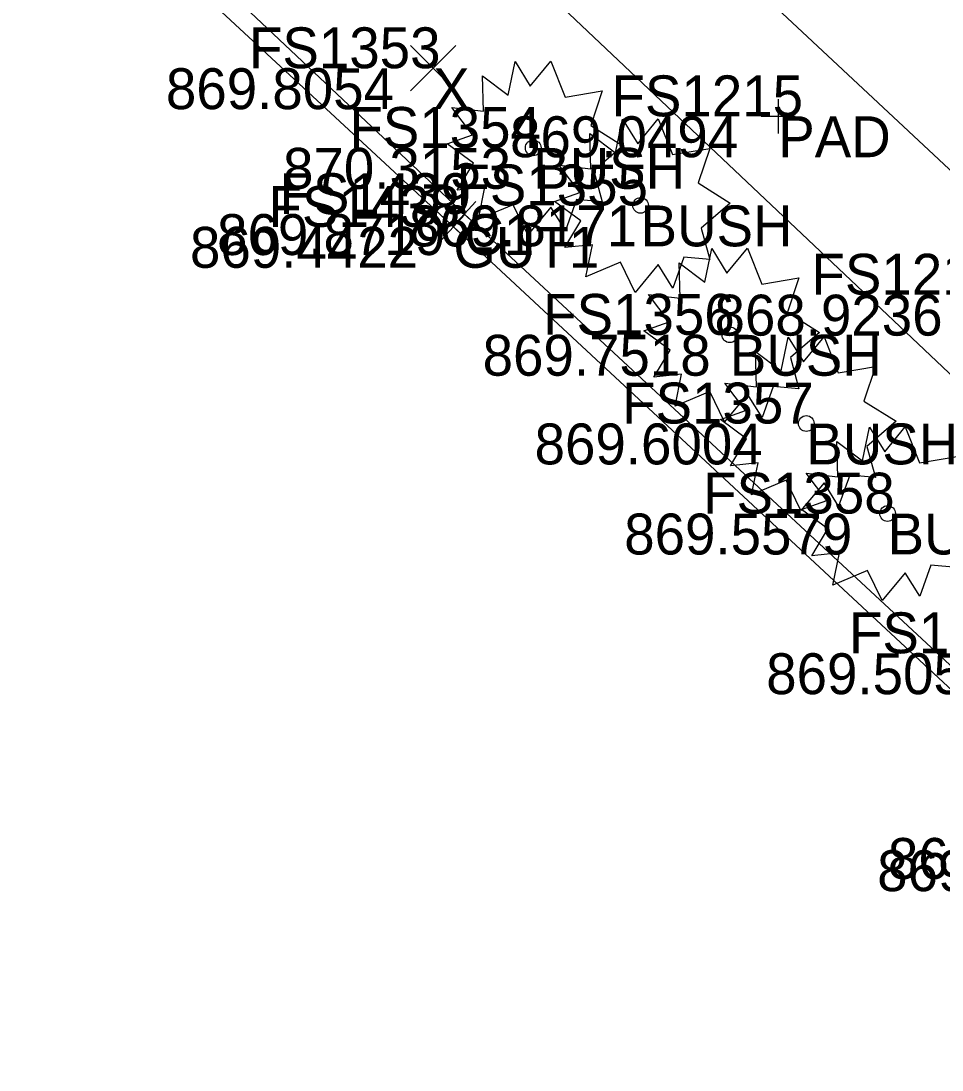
# Model space of a CAD drawing. Extents: x 1469677 to 1493262, y 375219 to 389293.
# Drawn here: x 1479642.82 to 1479669.85, y 379821.94 to 379852.72 of the extents above; entities that cross this region are included whole.
import ezdxf

# ---------------------------------------------------------------- set-up
doc = ezdxf.new("R2010")
doc.units = 0
for name, color, linetype in [('DV_X_Lot_Line', 7, 'Continuous'), ('DV_X_Text', 7, 'Continuous'), ('GK_Visualization', 7, 'Continuous'), ('PNTELEV', 7, 'Continuous'), ('RD_P_Text', 7, 'Continuous'), ('RW_P_Const_Limits', 7, 'Continuous'), ('RW_P_Esmt_SW', 7, 'Continuous'), ('RW_P_Esmt_U', 7, 'Continuous')]:
    doc.layers.add(name, color=color, linetype=linetype)

msp = doc.modelspace()

# ---------------------------------------------------------------- linework, layer by layer
at = {"layer": 'DV_X_Lot_Line'}
for points in [[(1479705.728, 379814.895), (1479685.769, 379833.709), (1479660.411, 379857.395), (1479657.292, 379860.626), (1479660.086, 379863.591), (1479659.321, 379864.377), (1479657.858, 379865.693), (1479656.248, 379867.188), (1479655.369, 379867.882), (1479654.27, 379866.26), (1479652.631, 379864.542), (1479652.351, 379864.607), (1479645.059, 379871.586), (1479642.188, 379874.12), (1479639.084, 379877.042), (1479636.766, 379877.319), (1479635.406, 379877.451), (1479631.457, 379877.615), (1479630.424, 379877.567), (1479629.778, 379877.526), (1479625.011, 379876.78), (1479605.984, 379871.904), (1479600.533, 379870.639), (1479580.734, 379865.6)], [(1479703.027, 379811.462), (1479682.443, 379830.686), (1479657.296, 379854.468), (1479652, 379859.64), (1479649.772, 379861.739), (1479651.803, 379859.818), (1479649.833, 379861.569), (1479642.24, 379868.777), (1479639.038, 379871.891), (1479636.885, 379872.56), (1479634.381, 379872.969), (1479631.754, 379873.282), (1479630.076, 379873.213), (1479625.848, 379872.765), (1479606.823, 379868.193), (1479601.313, 379866.859), (1479581.547, 379861.918)]]:
    msp.add_lwpolyline(points, dxfattribs=at)
at = {"layer": 'PNTELEV'}
for p, q in [((1479665.044, 379850.427), (1479665.044, 379849.427)), ((1479664.544, 379849.927), (1479665.544, 379849.927)), ((1479665.044, 379849.927), (1479665.044, 379849.927)), ((1479656.198, 379846.717), (1479655.466, 379847.397)), ((1479655.492, 379846.69), (1479656.172, 379847.423)), ((1479655.876, 379846.342), (1479655.144, 379847.023)), ((1479655.17, 379846.316), (1479655.85, 379847.048)), ((1479655.832, 379847.057), (1479655.832, 379847.057)), ((1479655.51, 379846.682), (1479655.51, 379846.682))]:
    msp.add_line(p, q, dxfattribs=at)
at = {"layer": 'RD_P_Text'}
for points in [[(1479752.341, 379756.82), (1479734.895, 379773.493), (1479717.229, 379789.662), (1479699.298, 379806.402), (1479688.16, 379794.934), (1479685.526, 379793.897), (1479682.733, 379795.157), (1479681.263, 379797.549), (1479682.493, 379800.746), (1479693.462, 379811.911), (1479675.554, 379828.75), (1479655.832, 379847.057), (1479640.191, 379861.809), (1479628.558, 379849), (1479624.614, 379847.664), (1479622.46, 379848.585), (1479618.996, 379850.857), (1479611.825, 379854.437), (1479601.319, 379856.892), (1479590.521, 379858.039)], [(1479751.933, 379756.629), (1479734.447, 379772.976), (1479716.701, 379789.463), (1479699.4, 379805.742), (1479688.561, 379794.786), (1479685.717, 379793.294), (1479682.291, 379794.8), (1479680.73, 379797.254), (1479682.169, 379801.19), (1479692.652, 379811.907), (1479675.183, 379828.391), (1479655.51, 379846.682), (1479640.151, 379860.926), (1479629.134, 379848.869), (1479624.571, 379847.215), (1479622.228, 379847.911), (1479618.757, 379850.398), (1479611.519, 379853.97), (1479601.347, 379856.369), (1479590.364, 379857.442)]]:
    msp.add_lwpolyline(points, dxfattribs=at)
at = {"layer": 'RW_P_Const_Limits'}
for points in [[(1479657.768, 379850.81), (1479658.373, 379851.545), (1479658.788, 379850.492), (1479659.88, 379850.672), (1479659.541, 379849.66), (1479660.486, 379849.065), (1479659.63, 379848.33), (1479659.88, 379847.417), (1479659.126, 379847.485), (1479658.801, 379846.572), (1479658.373, 379847.264), (1479657.695, 379846.447), (1479657.266, 379847.334), (1479656.246, 379846.904), (1479656.438, 379847.845), (1479655.626, 379847.762), (1479656.1, 379848.552), (1479655.331, 379849.12), (1479656.07, 379849.384), (1479655.463, 379850.187), (1479656.395, 379850.077), (1479656.365, 379851.115), (1479657.118, 379850.547), (1479657.325, 379851.532), (1479657.768, 379850.81)], [(1479660.919, 379849.121), (1479661.524, 379849.856), (1479661.939, 379848.803), (1479663.031, 379848.983), (1479662.692, 379847.971), (1479663.637, 379847.376), (1479662.781, 379846.641), (1479663.031, 379845.728), (1479662.277, 379845.796), (1479661.952, 379844.883), (1479661.524, 379845.574), (1479660.846, 379844.758), (1479660.417, 379845.644), (1479659.397, 379845.214), (1479659.589, 379846.156), (1479658.777, 379846.073), (1479659.251, 379846.863), (1479658.482, 379847.431), (1479659.221, 379847.694), (1479658.614, 379848.498), (1479659.546, 379848.388), (1479659.516, 379849.426), (1479660.269, 379848.858), (1479660.476, 379849.843), (1479660.919, 379849.121)], [(1479663.539, 379845.325), (1479664.144, 379846.06), (1479664.559, 379845.006), (1479665.651, 379845.186), (1479665.312, 379844.175), (1479666.257, 379843.58), (1479665.401, 379842.845), (1479665.651, 379841.931), (1479664.897, 379842), (1479664.572, 379841.086), (1479664.144, 379841.778), (1479663.466, 379840.961), (1479663.037, 379841.848), (1479662.017, 379841.418), (1479662.209, 379842.36), (1479661.397, 379842.276), (1479661.871, 379843.066), (1479661.102, 379843.635), (1479661.841, 379843.898), (1479661.234, 379844.701), (1479662.166, 379844.591), (1479662.136, 379845.63), (1479662.889, 379845.061), (1479663.096, 379846.046), (1479663.539, 379845.325)], [(1479665.782, 379842.723), (1479666.387, 379843.458), (1479666.802, 379842.404), (1479667.894, 379842.584), (1479667.555, 379841.573), (1479668.5, 379840.978), (1479667.644, 379840.243), (1479667.894, 379839.329), (1479667.14, 379839.398), (1479666.815, 379838.484), (1479666.387, 379839.176), (1479665.709, 379838.359), (1479665.28, 379839.246), (1479664.26, 379838.816), (1479664.452, 379839.758), (1479663.64, 379839.674), (1479664.114, 379840.464), (1479663.345, 379841.033), (1479664.084, 379841.296), (1479663.477, 379842.099), (1479664.409, 379841.989), (1479664.379, 379843.028), (1479665.132, 379842.459), (1479665.339, 379843.444), (1479665.782, 379842.723)], [(1479670.279, 379836.687), (1479669.525, 379836.755), (1479669.2, 379835.842), (1479668.772, 379836.534), (1479668.094, 379835.717), (1479667.665, 379836.604), (1479666.645, 379836.174), (1479666.837, 379837.115), (1479666.025, 379837.032), (1479666.499, 379837.822), (1479665.73, 379838.39), (1479666.469, 379838.654), (1479665.862, 379839.457), (1479666.794, 379839.347), (1479666.764, 379840.385), (1479667.517, 379839.817), (1479667.724, 379840.802), (1479668.167, 379840.08)], [(1479668.167, 379840.08), (1479668.772, 379840.815), (1479669.187, 379839.762), (1479670.279, 379839.942)]]:
    msp.add_lwpolyline(points, dxfattribs=at)
for centre in [(1479657.852, 379849.001), (1479661.003, 379847.312), (1479663.623, 379843.515), (1479665.866, 379840.913), (1479668.251, 379838.271)]:
    msp.add_circle(centre, 0.23, dxfattribs=at)
at = {"layer": 'RW_P_Esmt_U'}
for p, q in [((1479654.25, 379850.67), (1479655.584, 379852.005)), ((1479654.25, 379852.005), (1479655.584, 379850.67))]:
    msp.add_line(p, q, dxfattribs=at)

# ---------------------------------------------------------------- texts
at = {"layer": 'DV_X_Text'}
for s, p in [('869.8054', (1479647.075, 379850.137)), ('869.0494', (1479657.174, 379848.727)), ('870.3153', (1479650.512, 379847.8)), ('869.8171', (1479654.209, 379846.111)), ('869.8719', (1479648.576, 379845.857)), ('869.4422', (1479647.781, 379845.482)), ('868.9236', (1479663.173, 379843.492)), ('869.7518', (1479656.368, 379842.315)), ('869.6004', (1479657.893, 379839.713)), ('869.5579', (1479660.523, 379837.07)), ('869.5054', (1479664.689, 379832.971)), ('869.6132', (1479668.261, 379827.55)), ('869.1752', (1479667.946, 379827.191))]:
    msp.add_text(s, height=1.2, dxfattribs=at).set_placement(p)
at = {"layer": 'GK_Visualization'}
for s, p in [('X', (1479654.917, 379850.137)), ('PAD', (1479665.044, 379848.727)), ('BUSH', (1479657.853, 379847.8)), ('BUSH', (1479661.004, 379846.111)), ('C1', (1479655.832, 379845.857)), ('GUT1', (1479655.51, 379845.482)), ('BUSH', (1479663.624, 379842.315)), ('BUSH', (1479665.867, 379839.713)), ('BUSH', (1479668.252, 379837.07))]:
    msp.add_text(s, height=1.2, dxfattribs=at).set_placement(p)
at = {"layer": 'RW_P_Esmt_SW'}
for s, p in [('FS1353', (1479649.513, 379851.337)), ('FS1215', (1479660.151, 379849.927)), ('FS1354', (1479652.459, 379849)), ('FS1355', (1479655.6, 379847.311)), ('FS1439', (1479650.409, 379847.057)), ('FS1438', (1479650.087, 379846.682)), ('FS1216', (1479666.019, 379844.692)), ('FS1356', (1479658.145, 379843.515)), ('FS1357', (1479660.463, 379840.913)), ('FS1358', (1479662.839, 379838.27)), ('FS1359', (1479667.118, 379834.171))]:
    msp.add_text(s, height=1.2, dxfattribs=at).set_placement(p)

doc.saveas('drawing.dxf')
